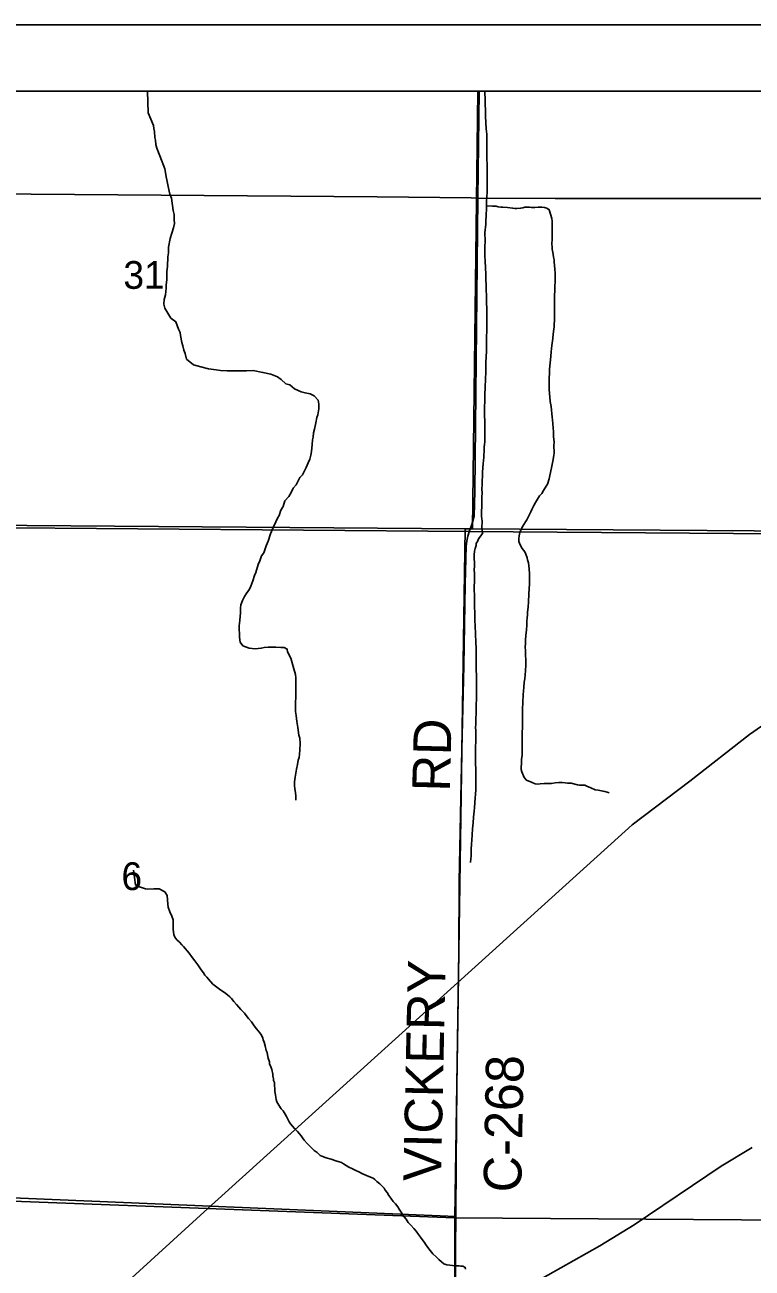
# Model space of a CAD drawing. Extents: x 0 to 34, y 0 to 22.
# Drawn here: x 3.554 to 4.651, y 19.126 to 21 of the extents above; entities that cross this region are included whole.
import ezdxf

# ---------------------------------------------------------------- set-up
doc = ezdxf.new("R2010")
doc.units = 0
for name, color, linetype in [('Default', 7, 'Continuous'), ('GM_X_County_Road', 7, 'Continuous'), ('GM_X_County_Road_Text', 7, 'Continuous'), ('GM_X_Minor_River', 7, 'Continuous'), ('GM_X_Rail_Line', 7, 'Continuous'), ('GM_X_Section', 7, 'Continuous'), ('GM_X_Section_Text', 7, 'Continuous'), ('GM_X_State_Route', 7, 'Continuous'), ('GM_X_Township_Road', 7, 'Continuous'), ('SH_Cut_Line', 7, 'Continuous'), ('SH_Data', 7, 'Continuous')]:
    doc.layers.add(name, color=color, linetype=linetype)

msp = doc.modelspace()

# ---------------------------------------------------------------- linework, layer by layer
at = {"layer": 'Default'}
for points in [[(4.2372, 20.9), (3.2415, 20.9), (3.2263, 20.248), (4.2182, 20.2402), (4.2288, 20.2402)], [(5.2431, 20.9), (4.2372, 20.9), (4.2288, 20.2402), (5.2199, 20.2335), (5.2336, 20.2342)]]:
    msp.add_lwpolyline(points, close=True, dxfattribs=at)
at = {"layer": 'GM_X_County_Road'}
for points in [[(4.2207, 20.2217), (4.2218, 20.2292), (4.2242, 20.236), (4.2282, 20.2469), (4.2313, 20.2594), (4.2323, 20.2973), (4.2372, 20.739), (4.2392, 20.9)], [(4.202, 19.0361), (4.2034, 19.0684), (4.2035, 19.1565), (4.2038, 19.204), (4.2045, 19.2851), (4.2055, 19.3997), (4.207, 19.4991), (4.2084, 19.602), (4.2091, 19.7086), (4.2111, 19.8096), (4.2129, 19.9079), (4.2157, 20.0339), (4.2181, 20.1571), (4.2197, 20.2141), (4.2207, 20.2217)]]:
    msp.add_lwpolyline(points, dxfattribs=at)
at = {"layer": 'GM_X_Minor_River'}
msp.add_line((3.7389, 20.9), (3.7398, 20.8676), dxfattribs=at)
for points in [[(4.2477, 20.9), (4.2476, 20.897), (4.248, 20.8886), (4.248, 20.8802), (4.2484, 20.8715), (4.2485, 20.8624), (4.2493, 20.8529), (4.2497, 20.8434), (4.2505, 20.8354), (4.2507, 20.7971), (4.2511, 20.7898), (4.2512, 20.7674), (4.2509, 20.7579), (4.251, 20.7484), (4.2506, 20.7405), (4.2503, 20.734), (4.2499, 20.7287), (4.25, 20.7196), (4.2496, 20.7169), (4.2496, 20.7116), (4.2489, 20.7051), (4.2489, 20.6994), (4.2478, 20.6865), (4.2479, 20.6743), (4.2476, 20.6652), (4.2476, 20.6516), (4.2481, 20.644), (4.2489, 20.6242), (4.2493, 20.6155), (4.2494, 20.6083), (4.2498, 20.6045), (4.2498, 20.5976), (4.2502, 20.5946), (4.2504, 20.5589), (4.2508, 20.5501), (4.2505, 20.5429), (4.2505, 20.5372), (4.2501, 20.5315), (4.2502, 20.5171), (4.2499, 20.5084), (4.2495, 20.4992), (4.2492, 20.4916), (4.2493, 20.4821), (4.2489, 20.4783), (4.2489, 20.4742), (4.2486, 20.4688), (4.2486, 20.4628), (4.2482, 20.4567), (4.2479, 20.451), (4.2475, 20.4453), (4.2476, 20.4331), (4.2473, 20.4233), (4.2474, 20.3906), (4.2478, 20.386), (4.2475, 20.3811), (4.2475, 20.3712), (4.2472, 20.3682), (4.2468, 20.3636), (4.2464, 20.3602), (4.2465, 20.3575), (4.2461, 20.3515), (4.2461, 20.3484), (4.2454, 20.3431), (4.245, 20.3382), (4.2447, 20.3328), (4.2443, 20.3252), (4.2437, 20.307), (4.2433, 20.3002), (4.2434, 20.2945), (4.243, 20.2884), (4.2431, 20.2736), (4.2427, 20.2671), (4.2428, 20.2625), (4.2428, 20.2595), (4.2432, 20.2553), (4.2436, 20.2523), (4.2436, 20.2485)], [(3.7398, 20.8676), (3.7479, 20.8482), (3.7483, 20.8437), (3.7494, 20.8395), (3.7502, 20.8304), (3.751, 20.8262), (3.7514, 20.8198), (3.753, 20.8141), (3.7565, 20.805), (3.7611, 20.7936), (3.7626, 20.7894), (3.7649, 20.783), (3.7661, 20.7773), (3.7669, 20.7708), (3.768, 20.7663), (3.77, 20.7564), (3.7727, 20.745), (3.775, 20.7386), (3.7778, 20.72), (3.7789, 20.7139), (3.7793, 20.7059), (3.7794, 20.7006), (3.7783, 20.6938), (3.773, 20.6782), (3.7708, 20.6649), (3.7705, 20.6565), (3.7698, 20.6504), (3.7691, 20.6356), (3.7683, 20.628), (3.768, 20.6162), (3.7673, 20.6075), (3.7673, 20.6029), (3.7666, 20.598), (3.7662, 20.5931), (3.764, 20.5862), (3.7633, 20.579), (3.7648, 20.5729), (3.774, 20.5581), (3.7816, 20.5525), (3.7859, 20.5415), (3.7882, 20.5362), (3.7886, 20.532), (3.7905, 20.521), (3.7921, 20.5161), (3.7936, 20.5096), (3.7955, 20.5047), (3.7975, 20.4963), (3.8085, 20.4873), (3.8192, 20.4847), (3.831, 20.4817), (3.8423, 20.4802), (3.8488, 20.4791), (3.8591, 20.4784), (3.8883, 20.4785), (3.8982, 20.479), (3.913, 20.476), (3.9248, 20.4734), (3.935, 20.4696), (3.9404, 20.4655), (3.9476, 20.4591), (3.9537, 20.4572), (3.9605, 20.4515), (3.9662, 20.4489), (3.9704, 20.447), (3.9765, 20.4451), (3.9841, 20.4437), (3.9902, 20.441), (3.9963, 20.4342), (3.9975, 20.4281), (3.9971, 20.4213), (3.9957, 20.4122), (3.9945, 20.408), (3.9927, 20.4), (3.9905, 20.3905), (3.9893, 20.3852), (3.9886, 20.3787), (3.9875, 20.3745), (3.9872, 20.3677), (3.9861, 20.3571), (3.985, 20.3514), (3.9838, 20.3453), (3.9812, 20.3399), (3.9782, 20.3327), (3.9726, 20.3217), (3.9684, 20.3175), (3.9632, 20.3068), (3.9586, 20.3015), (3.9556, 20.295), (3.9519, 20.2889), (3.9462, 20.2824), (3.9436, 20.274), (3.9402, 20.2683), (3.9376, 20.2603), (3.9349, 20.2562), (3.9323, 20.2508), (3.9282, 20.2421), (3.9244, 20.2329), (3.9207, 20.2215), (3.9181, 20.2147), (3.9143, 20.2044), (3.9106, 20.1998)], [(4.2499, 20.7272), (4.2594, 20.7268), (4.2647, 20.7265), (4.2678, 20.7257), (4.2719, 20.725), (4.275, 20.725), (4.2818, 20.7247), (4.2894, 20.7239), (4.2928, 20.7232), (4.2959, 20.7232), (4.3016, 20.7236), (4.305, 20.7244), (4.308, 20.7252), (4.3148, 20.7252), (4.3179, 20.7248), (4.3232, 20.7248), (4.3281, 20.7253), (4.3338, 20.7253), (4.3376, 20.7249), (4.341, 20.7238), (4.3448, 20.7212), (4.3487, 20.7079), (4.3491, 20.7041), (4.3492, 20.6767), (4.3489, 20.6703), (4.3493, 20.6646), (4.3493, 20.6619), (4.3505, 20.6543), (4.3513, 20.6498), (4.3521, 20.6456), (4.3521, 20.6426), (4.3529, 20.6372), (4.3533, 20.6319), (4.3537, 20.6258), (4.3537, 20.6126), (4.3534, 20.6065), (4.3531, 20.5993), (4.3527, 20.5924), (4.3527, 20.5875), (4.3529, 20.5586), (4.3522, 20.5449), (4.3518, 20.5411), (4.3507, 20.5339), (4.35, 20.5274), (4.3489, 20.5168), (4.3482, 20.5122), (4.3478, 20.5073), (4.3464, 20.4944), (4.346, 20.491), (4.3457, 20.4856), (4.3453, 20.4811), (4.3453, 20.4761), (4.3446, 20.4663), (4.3447, 20.4503), (4.3451, 20.4446), (4.3459, 20.4321), (4.3475, 20.4245), (4.3491, 20.4085), (4.3495, 20.4044), (4.3503, 20.3987), (4.3511, 20.3865), (4.3511, 20.3793), (4.3523, 20.3709), (4.3519, 20.366), (4.352, 20.355), (4.3516, 20.3508), (4.3502, 20.3424), (4.3487, 20.3348), (4.3465, 20.325), (4.3457, 20.3208), (4.3446, 20.3158), (4.342, 20.3078), (4.3401, 20.3048), (4.3363, 20.2983), (4.3337, 20.2937), (4.3303, 20.2899), (4.3269, 20.285), (4.3239, 20.28), (4.3213, 20.2755), (4.3198, 20.2724), (4.3183, 20.2697), (4.3168, 20.2659), (4.3145, 20.261), (4.3123, 20.2568), (4.3108, 20.2538), (4.3089, 20.2507), (4.3066, 20.2469), (4.3032, 20.2416), (4.3017, 20.2385), (4.3006, 20.2347), (4.2995, 20.2298), (4.2991, 20.226), (4.2991, 20.2214), (4.2999, 20.2188), (4.3015, 20.215), (4.3041, 20.2108), (4.308, 20.2055), (4.3095, 20.2021), (4.3114, 20.1964), (4.3118, 20.1934), (4.3134, 20.1892)], [(4.2436, 20.2485), (4.2432, 20.2455), (4.2432, 20.2428), (4.2436, 20.2371), (4.2444, 20.2341), (4.2418, 20.2299), (4.238, 20.2253), (4.2369, 20.2223), (4.2346, 20.2181), (4.2343, 20.2154), (4.2332, 20.2108), (4.232, 20.2067), (4.2317, 20.2013), (4.2318, 20.1835), (4.2314, 20.1789), (4.2318, 20.1725), (4.2319, 20.1592), (4.2315, 20.155), (4.2316, 20.1459), (4.232, 20.1428), (4.232, 20.1303), (4.2321, 20.1238), (4.2325, 20.1128), (4.2326, 20.1014), (4.233, 20.0946), (4.2334, 20.0817), (4.2334, 20.0786), (4.2338, 20.0726), (4.2339, 20.0692), (4.2343, 20.0604), (4.2344, 20.0464), (4.2348, 20.0357), (4.2348, 20.027), (4.2349, 20.0202), (4.2351, 19.9826), (4.2347, 19.9765), (4.2344, 19.9689), (4.2344, 19.9617), (4.234, 19.9556), (4.2341, 19.9461), (4.2337, 19.9411), (4.2338, 19.9362), (4.2339, 19.9183), (4.2335, 19.9134), (4.2336, 19.8845), (4.234, 19.88), (4.2342, 19.8564), (4.2338, 19.853), (4.2338, 19.85), (4.2338, 19.8473), (4.2335, 19.8401), (4.2331, 19.8348), (4.2321, 19.82), (4.2317, 19.8146), (4.2306, 19.8055), (4.2299, 19.7972), (4.2292, 19.788), (4.2285, 19.7793), (4.2278, 19.7709), (4.2274, 19.7652), (4.2274, 19.7626), (4.2271, 19.7599), (4.2271, 19.7497), (4.2271, 19.7466), (4.2264, 19.7432), (4.226, 19.7375)], [(3.9106, 20.1998), (3.9083, 20.1922), (3.9057, 20.1865), (3.9023, 20.1747), (3.9001, 20.1701), (3.8978, 20.1618), (3.8948, 20.1538), (3.8926, 20.1492), (3.8877, 20.1423), (3.8854, 20.1382), (3.8824, 20.1324), (3.8798, 20.126), (3.8791, 20.1207), (3.8791, 20.1131), (3.8788, 20.1085), (3.878, 20.102), (3.8773, 20.0941), (3.8774, 20.077), (3.8786, 20.0697), (3.8828, 20.0641), (3.8923, 20.0603), (3.9014, 20.0596), (3.9105, 20.0604), (3.9147, 20.0612), (3.9211, 20.062), (3.9325, 20.062), (3.9401, 20.0613), (3.945, 20.0613), (3.9496, 20.0591), (3.95, 20.0549), (3.955, 20.0454), (3.9596, 20.0295), (3.9623, 20.0208), (3.9627, 20.0158), (3.9628, 20.0003), (3.9625, 19.9904), (3.9625, 19.9862), (3.9621, 19.979), (3.9622, 19.9649), (3.963, 19.9588), (3.9642, 19.9501), (3.9658, 19.941), (3.9673, 19.9292), (3.9685, 19.9247), (3.9689, 19.9167), (3.9686, 19.9065), (3.9682, 19.9008), (3.9675, 19.8958), (3.966, 19.8916), (3.9653, 19.8852), (3.9634, 19.8779), (3.9616, 19.8658), (3.9605, 19.8589), (3.9605, 19.8532), (3.9609, 19.8483), (3.9621, 19.843), (3.9625, 19.8373), (3.9625, 19.8312)], [(4.3134, 20.1892), (4.3138, 20.1846), (4.3145, 20.1801), (4.315, 20.1725), (4.315, 20.1573), (4.3147, 20.1501), (4.314, 20.1421), (4.3133, 20.1299), (4.3129, 20.1227), (4.3122, 20.1143), (4.3122, 20.1098), (4.3115, 20.1071), (4.3111, 20.1003), (4.3108, 20.095), (4.3104, 20.0881), (4.3097, 20.0794), (4.309, 20.0729), (4.3087, 20.0672), (4.3083, 20.0623), (4.3087, 20.0566), (4.3087, 20.0498), (4.3092, 20.0429), (4.3092, 20.0353), (4.3089, 20.0262), (4.3078, 20.014), (4.307, 20.0091), (4.3063, 20.0015), (4.306, 19.9954), (4.3056, 19.9905), (4.3053, 19.9871), (4.3049, 19.9821), (4.3049, 19.976), (4.3046, 19.9711), (4.3046, 19.9654), (4.3043, 19.9567), (4.3044, 19.9396), (4.304, 19.935), (4.3041, 19.9069), (4.3038, 19.9016), (4.3038, 19.8989), (4.3034, 19.8963), (4.3031, 19.8928), (4.3031, 19.8898), (4.3027, 19.8856), (4.3024, 19.8822), (4.3024, 19.8776), (4.3032, 19.8742), (4.3059, 19.8682), (4.307, 19.8655), (4.3104, 19.8614), (4.3188, 19.858), (4.3234, 19.8557), (4.3264, 19.8553), (4.3313, 19.8558), (4.337, 19.8562), (4.3427, 19.8566), (4.348, 19.8562), (4.3537, 19.8574), (4.359, 19.8582), (4.3644, 19.8582), (4.3689, 19.8575), (4.3723, 19.8571), (4.3777, 19.8567), (4.3875, 19.8545), (4.3902, 19.8541), (4.3985, 19.8538), (4.4016, 19.8523), (4.4073, 19.85), (4.4141, 19.847), (4.4187, 19.8463), (4.4259, 19.8448), (4.4286, 19.8444), (4.432, 19.8433), (4.435, 19.8422)], [(3.7178, 19.7256), (3.7206, 19.7036), (3.7252, 19.7013), (3.7316, 19.6991), (3.7358, 19.6979), (3.7388, 19.6972), (3.7487, 19.6976), (3.7567, 19.6977), (3.7651, 19.6931), (3.7685, 19.6878), (3.7693, 19.681), (3.7697, 19.6746), (3.7701, 19.67), (3.7728, 19.6632), (3.7755, 19.6567), (3.7774, 19.651), (3.7775, 19.637), (3.7779, 19.6324), (3.7787, 19.629), (3.7802, 19.6248), (3.7833, 19.6207), (3.7871, 19.6173), (3.7905, 19.6135), (3.7932, 19.6105), (3.7962, 19.6071), (3.7989, 19.6044), (3.8016, 19.6006), (3.8054, 19.5957), (3.8104, 19.5893), (3.8146, 19.5832), (3.8199, 19.5757), (3.8234, 19.5711), (3.8253, 19.5677), (3.8283, 19.5647), (3.831, 19.5616), (3.8375, 19.5541), (3.8497, 19.545), (3.855, 19.5412), (3.8596, 19.5379), (3.863, 19.5348), (3.8657, 19.5322), (3.8691, 19.528), (3.8729, 19.5231), (3.8764, 19.5193), (3.8798, 19.5159), (3.8825, 19.5129), (3.8852, 19.5102), (3.8878, 19.5068), (3.8913, 19.5023), (3.8955, 19.497), (3.8997, 19.4913), (3.9031, 19.4864), (3.9058, 19.4834), (3.9081, 19.4807), (3.9108, 19.4769), (3.9127, 19.4728), (3.9135, 19.4701), (3.9146, 19.4663), (3.9162, 19.461), (3.9181, 19.4542), (3.9192, 19.4508), (3.92, 19.4474), (3.9208, 19.4424), (3.9227, 19.4371), (3.9231, 19.4341), (3.925, 19.4295), (3.9262, 19.4254), (3.9278, 19.4185), (3.9278, 19.4159), (3.9289, 19.4113), (3.9289, 19.4087), (3.9305, 19.4056), (3.9305, 19.4014), (3.9309, 19.3961), (3.9309, 19.3923), (3.9317, 19.387), (3.9325, 19.3832), (3.9329, 19.3802), (3.934, 19.3768), (3.9371, 19.3715), (3.9405, 19.3662), (3.9436, 19.3628), (3.9463, 19.3578), (3.9486, 19.3544), (3.9509, 19.3495), (3.9524, 19.3465), (3.9547, 19.3434), (3.9604, 19.3366), (3.965, 19.3317), (3.9681, 19.3283), (3.9707, 19.3253), (3.9726, 19.3223), (3.9753, 19.3188), (3.9795, 19.3139), (3.9849, 19.3086), (3.9902, 19.303), (3.9948, 19.3), (3.9993, 19.2958), (4.002, 19.2947), (4.0085, 19.2924), (4.0157, 19.2902)], [(4.0157, 19.2902), (4.0229, 19.2879), (4.0279, 19.2864), (4.0313, 19.2849), (4.0347, 19.283), (4.0385, 19.2808), (4.0423, 19.2781), (4.0469, 19.2759), (4.0511, 19.274), (4.0595, 19.2699), (4.0621, 19.2687), (4.069, 19.2654), (4.0728, 19.2642), (4.0792, 19.2616), (4.0819, 19.2597), (4.085, 19.2567), (4.0891, 19.2529), (4.093, 19.2495), (4.0956, 19.2465), (4.0975, 19.2435), (4.1002, 19.2397), (4.1029, 19.2355), (4.106, 19.2313), (4.1094, 19.2264), (4.1128, 19.2226), (4.1163, 19.2181), (4.1186, 19.2147), (4.1212, 19.2101), (4.1235, 19.2067), (4.1258, 19.2033), (4.1289, 19.1999), (4.1319, 19.1946), (4.1358, 19.1905), (4.1403, 19.1859), (4.1442, 19.1814), (4.1476, 19.1768), (4.1507, 19.1727), (4.1533, 19.1689), (4.1564, 19.1647), (4.1583, 19.1621), (4.1617, 19.1572), (4.1652, 19.1526), (4.1694, 19.1477), (4.174, 19.1428), (4.1782, 19.139), (4.1823, 19.1352), (4.1858, 19.1322), (4.1903, 19.1307), (4.1949, 19.1303), (4.1991, 19.13), (4.2021, 19.1296), (4.2055, 19.1296), (4.209, 19.1293), (4.2116, 19.1289), (4.2143, 19.1289), (4.2181, 19.127), (4.2185, 19.1244)]]:
    msp.add_lwpolyline(points, dxfattribs=at)
at = {"layer": 'GM_X_Rail_Line'}
msp.add_lwpolyline([(2.3438, 17.8832), (2.4082, 17.9379), (2.5423, 18.061), (2.7943, 18.2844), (3.1322, 18.5996), (3.3125, 18.7514), (3.4225, 18.8451), (3.8301, 19.2157), (4.2487, 19.5941), (4.47, 19.794), (4.5566, 19.8598), (4.6465, 19.9302), (4.7011, 19.9679), (5.2057, 20.3431), (5.7213, 20.7403), (5.9437, 20.9)], dxfattribs=at)
at = {"layer": 'GM_X_Section'}
for points in [[(3.2263, 20.248), (4.2182, 20.2402), (4.2026, 19.2018), (3.2151, 19.2391)], [(4.2182, 20.2402), (4.2288, 20.2402), (5.2199, 20.2335), (5.2108, 19.1947), (4.2026, 19.2018)], [(3.2151, 19.2391), (4.2026, 19.2018), (4.1997, 18.1993), (3.2, 18.2405)], [(4.2026, 19.2018), (5.2108, 19.1947), (5.2018, 18.1949), (4.1997, 18.1993)]]:
    msp.add_lwpolyline(points, close=True, dxfattribs=at)
at = {"layer": 'GM_X_State_Route'}
msp.add_lwpolyline([(3.2071, 18.5344), (3.2912, 18.5707), (3.438, 18.6337), (3.6313, 18.7164), (3.7384, 18.7627), (3.8083, 18.7947), (3.868, 18.8264), (3.9451, 18.8676), (4.0083, 18.9108), (4.0708, 18.9549), (4.1126, 18.9832), (4.1555, 19.0093), (4.202, 19.0361), (4.323, 19.1042), (4.4211, 19.1597), (4.4727, 19.1914), (4.604, 19.2798), (4.6509, 19.3078)], dxfattribs=at)
at = {"layer": 'GM_X_Township_Road'}
msp.add_line((3.2146, 19.245), (4.2038, 19.204), dxfattribs=at)
msp.add_lwpolyline([(8.9, 20.2053), (8.9, 20.9), (3.2412, 20.9), (3.2371, 20.748), (3.2241, 20.2443), (4.224, 20.2365), (5.2207, 20.2288), (6.0936, 20.222), (6.4763, 20.2191), (7.2271, 20.2132)], close=True, dxfattribs=at)
for points in [[(3.2373, 20.7474), (4.0851, 20.7407), (4.2272, 20.7391)], [(4.2272, 20.7391), (4.2372, 20.739), (4.3538, 20.7384), (5.241, 20.7384)], [(8.9, 14.1483), (8.9, 20.2053), (7.2271, 20.2132), (6.4763, 20.2191), (6.0936, 20.222), (5.2207, 20.2288), (4.224, 20.2365), (3.2241, 20.2443), (3.2118, 19.2455), (3.2116, 19.2346), (3.2069, 18.535), (3.1896, 17.5787), (3.1895, 17.5705), (3.1894, 17.563), (3.1774, 16.6219), (3.1774, 16.6199), (3.1628, 15.2158), (3.1576, 14.794), (3.1491, 14.2171)]]:
    msp.add_lwpolyline(points, dxfattribs=at)
at = {"layer": 'SH_Cut_Line'}
msp.add_lwpolyline([(8.9, 14.1483), (8.9, 20.9), (2.1, 20.9), (2.1, 14.2219)], dxfattribs=at)
at = {"layer": 'SH_Data'}
for p, q in [((2, 21), (9, 21)), ((2.1, 20.9), (8.9, 20.9))]:
    msp.add_line(p, q, dxfattribs=at)

# ---------------------------------------------------------------- texts
at = {"layer": 'GM_X_County_Road_Text'}
for s, rotation, p in [('RD', 88.5193, (4.1948, 19.8438)), ('VICKERY', 88.7614, (4.1814, 19.2563)), ('C-268', 88.8978, (4.3024, 19.2397))]:
    msp.add_text(s, height=0.05682, rotation=rotation, dxfattribs=at).set_placement(p)
at = {"layer": 'GM_X_Section_Text'}
for s, height, p in [('31', 0.04186, (3.7025, 20.6021)), ('6', 0.0419, (3.6996, 19.6958))]:
    msp.add_text(s, height=height, rotation=0, dxfattribs=at).set_placement(p)

doc.saveas('drawing.dxf')
